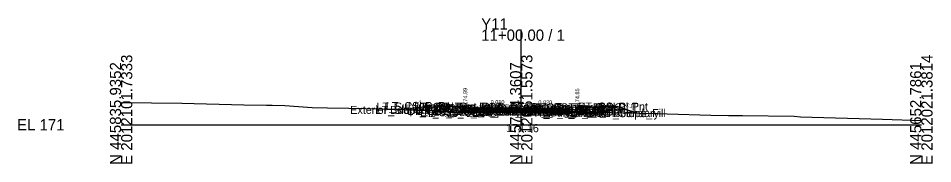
# Model space of a CAD drawing. Extents: x -26 to 203, y -10 to 3517.
# Drawn here: x -25.7 to 202.8, y 1990.3 to 2026.5 of the extents above; entities that cross this region are included whole.
import ezdxf

# ---------------------------------------------------------------- set-up
doc = ezdxf.new("R2010")
doc.units = 0
for name, color, linetype in [('Default', 7, 'Continuous'), ('Exist Cross Section Cell', 7, 'Continuous'), ('Exist XS Center Line Elevation Label', 7, 'Continuous'), ('Exist XS Ground Line', 7, 'Continuous'), ('Prop CMT Conc Surface', 7, 'Continuous'), ('Prop CMT Concrete Structures', 7, 'Continuous'), ('Prop CMT Pvmt Course 1', 7, 'Continuous'), ('Prop CMT Pvmt Course 1 CG', 7, 'Continuous'), ('Prop CMT Pvmt Course 2', 7, 'Continuous'), ('Prop CMT Pvmt Course 3', 7, 'Continuous'), ('Prop CMT Pvmt Surface', 7, 'Continuous'), ('Prop CMT Slope Grass', 7, 'Continuous'), ('Prop CMT Subgrade Earthwork', 7, 'Continuous'), ('Prop XS Earthwork Shape', 7, 'Continuous'), ('Prop XS Hydro Elevations', 7, 'Continuous'), ('Prop XS SE Text', 7, 'Continuous'), ('Prop XS Side Slope Text', 7, 'Continuous'), ('Scratch_Level_0', 7, 'Continuous')]:
    doc.layers.add(name, color=color, linetype=linetype)

msp = doc.modelspace()

# ---------------------------------------------------------------- linework, layer by layer
at = {"layer": 'Exist Cross Section Cell'}
for p, q in [((100, 2000), (100, 2023.74)), ((0, 2000), (100, 2000)), ((100, 2000), (200, 2000))]:
    msp.add_line(p, q, dxfattribs=at)
at = {"layer": 'Exist XS Ground Line'}
msp.add_lwpolyline([(0, 2005.54), (15.17, 2005.37), (30.66, 2004.95), (36.38, 2004.93), (37.01, 2004.89), (37.78, 2004.85), (40.93, 2004.77), (47.77, 2004.34), (51.6, 2004.22), (56.94, 2004.12), (69.39, 2003.89), (70.7, 2003.85), (72.92, 2003.73), (87.21, 2003.05), (87.65, 2003), (88.79, 2002.94), (98.19, 2003.14), (99.9, 2003.16), (100.64, 2003.14), (111.79, 2002.73), (112.81, 2002.89), (112.84, 2003.13), (115.11, 2003.04), (116.11, 2003.06), (119.51, 2003.19), (122.52, 2003.07), (132.97, 2002.81), (136.49, 2002.72), (147.37, 2002.43), (151.8, 2002.29), (155.27, 2002.28), (168.2, 2002.11), (169.76, 2002), (190.29, 2001.4), (200, 2001.1)], dxfattribs=at)
at = {"layer": 'Prop CMT Conc Surface'}
for points in [[(86, 2003.99), (86, 2004.49), (85.5, 2004.49)], [(114, 2003.85), (114, 2004.35), (114.5, 2004.35)], [(88, 2004.09), (86, 2003.99)], [(112, 2003.97), (114, 2003.85)]]:
    msp.add_lwpolyline(points, dxfattribs=at)
at = {"layer": 'Prop CMT Concrete Structures'}
for points in [[(88, 2004.09), (86, 2003.99), (86, 2004.49), (85.5, 2004.49)], [(85.5, 2004.49), (85.5, 2003.48), (88, 2003.5)], [(112, 2003.97), (114, 2003.85), (114, 2004.35), (114.5, 2004.35)], [(114.5, 2004.35), (114.5, 2003.33), (112, 2003.38)], [(88, 2003.5), (88, 2004.09)], [(112, 2003.38), (112, 2003.97)]]:
    msp.add_lwpolyline(points, dxfattribs=at)
at = {"layer": 'Prop CMT Pvmt Course 1'}
for points in [[(100, 2004.21), (88, 2004.09)], [(88, 2004.09), (88, 2003.84)], [(88, 2003.84), (100, 2003.96)], [(100, 2003.96), (100, 2004.21)], [(100, 2004.21), (112, 2003.97)], [(100, 2003.96), (100, 2004.21)], [(112, 2003.72), (100, 2003.96)], [(112, 2003.97), (112, 2003.72)]]:
    msp.add_lwpolyline(points, dxfattribs=at)
msp.add_lwpolyline([(100, 2003.96), (100, 2004.08), (100, 2004.08), (100, 2003.96)], close=True, dxfattribs=at)
msp.add_lwpolyline([(100, 2003.96), (100, 2004.08), (100, 2004.08), (100, 2003.96)], close=True, dxfattribs=at)
at = {"layer": 'Prop CMT Pvmt Course 1 CG'}
for points in [[(88, 2003.5), (85, 2003.47), (84.66, 2003.14)], [(84.66, 2003.14), (88, 2003.17)], [(88, 2003.17), (88, 2003.5)], [(112, 2003.38), (115, 2003.32), (115.34, 2002.98)], [(112, 2003.05), (112, 2003.38)], [(115.34, 2002.98), (112, 2003.05)]]:
    msp.add_lwpolyline(points, dxfattribs=at)
at = {"layer": 'Prop CMT Pvmt Course 2'}
for points in [[(100, 2003.96), (88, 2003.84)], [(88, 2003.84), (88, 2003.5)], [(88, 2003.5), (100, 2003.62)], [(100, 2003.62), (100, 2003.96)], [(100, 2003.62), (100, 2003.96)], [(100, 2003.96), (112, 2003.72)], [(112, 2003.38), (100, 2003.62)], [(112, 2003.72), (112, 2003.38)]]:
    msp.add_lwpolyline(points, dxfattribs=at)
at = {"layer": 'Prop CMT Pvmt Course 3'}
for points in [[(100, 2003.62), (88, 2003.5)], [(88, 2003.5), (88, 2003.17)], [(88, 2003.17), (100, 2003.29)], [(100, 2003.29), (100, 2003.62)], [(100, 2003.62), (112, 2003.38)], [(100, 2003.29), (100, 2003.62)], [(112, 2003.05), (100, 2003.29)], [(112, 2003.38), (112, 2003.05)]]:
    msp.add_lwpolyline(points, dxfattribs=at)
at = {"layer": 'Prop CMT Pvmt Surface'}
for points in [[(100, 2004.21), (88, 2004.09)], [(100, 2004.21), (112, 2003.97)]]:
    msp.add_lwpolyline(points, dxfattribs=at)
at = {"layer": 'Prop CMT Slope Grass'}
for points in [[(85.5, 2004.49), (76, 2004.68), (73.14, 2003.72)], [(114.5, 2004.35), (124, 2004.54), (128.87, 2002.91)]]:
    msp.add_lwpolyline(points, dxfattribs=at)
at = {"layer": 'Prop CMT Subgrade Earthwork'}
for points in [[(88, 2003.17), (84.66, 2003.14), (83.27, 2004.53)], [(112, 2003.05), (115.34, 2002.98), (116.75, 2004.39)], [(100, 2003.29), (88, 2003.17)], [(100, 2003.29), (112, 2003.05)]]:
    msp.add_lwpolyline(points, dxfattribs=at)
at = {"layer": 'Prop XS Earthwork Shape'}
for points in [[(83.27, 2004.53), (76, 2004.68), (73.14, 2003.72), (84.62, 2003.18)], [(119.51, 2003.19), (122.52, 2003.07), (128.87, 2002.91), (124, 2004.54), (116.75, 2004.39), (115.4, 2003.05), (116.11, 2003.06)], [(84.62, 2003.18), (85.31, 2003.14), (84.66, 2003.14)], [(100.64, 2003.14), (111.79, 2002.73), (112.81, 2002.89), (112.83, 2003.03), (112, 2003.05), (100, 2003.29), (88, 2003.17), (85.31, 2003.14), (87.21, 2003.05), (87.65, 2003), (88.79, 2002.94), (98.19, 2003.14), (99.9, 2003.16)], [(112.84, 2003.13), (115.11, 2003.04), (115.4, 2003.05), (115.34, 2002.98), (112.83, 2003.03)]]:
    msp.add_lwpolyline(points, close=True, dxfattribs=at)

# ---------------------------------------------------------------- texts
at = {"layer": 'Default'}
msp.add_text('-', height=0.0001, dxfattribs=at).set_placement((0, 2000))
at = {"layer": 'Exist Cross Section Cell'}
for s, p in [('Y11', (90, 2023.74)), ('11+00.00 / 1', (90, 2020.94)), ('EL 171', (-26, 1998.6))]:
    msp.add_text(s, height=2.8, dxfattribs=at).set_placement(p)
for s, p in [('E 2012101.7333', (2.8, 1990)), ('E 2012061.5573', (102.8, 1990)), ('E 2012021.3814', (202.8, 1990)), ('N 445835.9352', (0, 1990)), ('N 445744.3607', (100, 1990)), ('N 445652.7861', (200, 1990))]:
    msp.add_text(s, height=2.8, rotation=90, dxfattribs=at).set_placement(p)
at = {"layer": 'Exist XS Center Line Elevation Label'}
msp.add_text('174.16', height=2, dxfattribs=at).set_placement((96.21, 1998.16))
at = {"layer": 'Prop XS Hydro Elevations'}
for s, p in [('174.99', (86.5, 2004.99)), ('174.85', (114.5, 2004.85))]:
    msp.add_text(s, height=1, rotation=90, dxfattribs=at).set_placement(p)
at = {"layer": 'Prop XS SE Text'}
for s, rotation, p in [('0.010', 0.5729, (92.36, 2005.13)), ('0.020', 358.8542, (104.27, 2005.12))]:
    msp.add_text(s, height=1, rotation=rotation, dxfattribs=at).set_placement(p)
at = {"layer": 'Prop XS Side Slope Text'}
for rotation, p in [(18.4332, (73.58, 2004.66)), (341.5668, (125.92, 2004.69))]:
    msp.add_text('3:1', height=1, rotation=rotation, dxfattribs=at).set_placement(p)
at = {"layer": 'Scratch_Level_0'}
for s, p in [('Exterior Boundary', (57.28, 2002.72)), ('LT_Slope_Fill', (63.66, 2002.72)), ('LT_Sub_Trench_Out_DLT', (63.84, 2003.53)), ('LT_CSLP_Pnt', (66.17, 2003.68)), ('LT_CG1_Shelf_Out', (71.55, 2002.47)), ('LT_CG_Top_Face', (73.26, 2003.49)), ('LT_CG_Top_BOC', (73.78, 2003.49)), ('LT_CG_Bot_BOC', (73.81, 2002.48)), ('LT_CG_Top_Gut', (74.24, 2002.99)), ('LT_Sub_OEOP', (74.77, 2002.14)), ('LT_CG_Bot_IE', (77.91, 2002.5)), ('LT_Sub_OEOT', (78.08, 2002.17)), ('LT_PV2_OEOT', (78.17, 2002.84)), ('LT_PV3_OEOT', (78.17, 2002.5)), ('LT_PV1_OEOT', (78.74, 2003.09)), ('RT_Sub_OEEOP', (89.17, 2002.29)), ('LT_Sub_OEEOP', (89.21, 2002.29)), ('RT_PV2_OEEOP', (89.26, 2002.96)), ('RT_PV3_OEEOP', (89.26, 2002.62)), ('LT_PV2_OEEOP', (89.31, 2002.96)), ('LT_PV3_OEEOP', (89.31, 2002.62)), ('RT_PV1_OEEOP', (89.83, 2003.08)), ('LT_PV1_OEEOP', (89.87, 2003.08)), ('RT_PV2_IEEOP', (89.91, 2002.96)), ('LT_PV2_IEEOP', (89.95, 2002.96)), ('RT_PV1_IEEOP', (90.47, 2003.08)), ('LT_PV1_IEEOP', (90.52, 2003.08)), ('PV2_PGL', (93.91, 2002.96)), ('PV1_PGL', (94.47, 2003.21)), ('RT_Sub_Trench_Out_DLT', (97.27, 2003.39)), ('RT_CG_Top_Face', (101.21, 2003.35)), ('RT_CG1_Shelf_Out', (101.5, 2002.32)), ('RT_CG_Bot_IE', (101.87, 2002.38)), ('RT_PV2_OEOT', (102.13, 2002.72)), ('RT_PV3_OEOT', (102.13, 2002.38)), ('RT_CG_Top_Gut', (102.19, 2002.85)), ('RT_PV1_OEOT', (102.69, 2002.97)), ('RT_CG_Top_BOC', (102.74, 2003.35)), ('RT_CG_Bot_BOC', (102.77, 2002.33)), ('RT_CSLP_Pnt', (114.13, 2003.54)), ('RT_Sub_OEOT', (102.03, 2002.05)), ('RT_Sub_OEOP', (105.4, 2001.98)), ('Exterior Boundary', (113.02, 2001.91)), ('RT_Slope_Fill', (119.35, 2001.91))]:
    msp.add_text(s, height=2, dxfattribs=at).set_placement(p)

doc.saveas('drawing.dxf')
